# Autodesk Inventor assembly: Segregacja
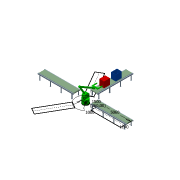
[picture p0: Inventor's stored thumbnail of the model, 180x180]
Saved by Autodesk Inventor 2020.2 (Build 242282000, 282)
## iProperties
Manager: www.cadconsulting.pl
Company: Fabian Stasiak CAD Consulting
Created: 2006-01
Part Number: Segregacja
Document SubType Name: Assembly
Designer: F.Stasiak
Author: F.Stasiak
Subject: Zbiór ćwiczeń. Autodesk Inventor 2020. Kurs podstawowy
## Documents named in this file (6)
- C:\2020_Kurs_podstawowy\R7 Prezentacje\900_Segregacja.iam
- C:\2020_Kurs_podstawowy\R7 Prezentacje\Komponenty\Przenośnik.ipt
- C:\2020_Kurs_podstawowy\R7 Prezentacje\Komponenty\Schemat.ipt
- C:\2020_Kurs_podstawowy\R7 Prezentacje\Komponenty\Robot.ipt
- C:\2020_Kurs_podstawowy\R7 Prezentacje\Komponenty\Paczka1.ipt
- C:\2020_Kurs_podstawowy\R7 Prezentacje\Komponenty\Paczka2.ipt
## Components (7 placed, 5 different names)
1. Schemat:1 — Równoległy:1, Zestawiający:1, Zestawiający:2, Zestawiający:3, Zestawiający:4
2. Robot:1 — Zestawiający:4, Zestawiający:5, Kąt:1, Zestawiający:8, Zestawiający:9
3. Paczka1:1 — Zestawiający:8, Zestawiający:9, Równoległy:4, Zestawiający:10, Zestawiający:11
4. Paczka2:1 — Równoległy:4, Zestawiający:10, Zestawiający:12
5. Przenośnik:1 — Zestawiający:1, Zestawiający:2, Zestawiający:3
6. Przenośnik:2 — Zestawiający:11, Zestawiający:12
7. Przenośnik:3
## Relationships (13: Mate 10, Flush 2, Angle 1)
- Równoległy:1 [Flush]: Schemat:1
- Zestawiający:1 [Mate]: Schemat:1 ↔ Przenośnik:1
- Zestawiający:2 [Mate]: Schemat:1 ↔ Przenośnik:1
- Zestawiający:3 [Mate]: Schemat:1 ↔ Przenośnik:1
- Zestawiający:4 [Mate]: Schemat:1 ↔ Robot:1
- Zestawiający:5 [Mate]: Robot:1
- Kąt:1 [Angle]: Robot:1
- Zestawiający:8 [Mate]: Robot:1 ↔ Paczka1:1
- Zestawiający:9 [Mate]: Robot:1 ↔ Paczka1:1
- Równoległy:4 [Flush]: Paczka1:1 ↔ Paczka2:1
- Zestawiający:10 [Mate]: Paczka1:1 ↔ Paczka2:1
- Zestawiający:11 [Mate]: Paczka1:1 ↔ Przenośnik:2
- Zestawiający:12 [Mate]: Paczka2:1 ↔ Przenośnik:2
